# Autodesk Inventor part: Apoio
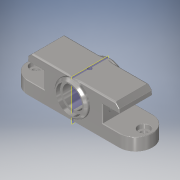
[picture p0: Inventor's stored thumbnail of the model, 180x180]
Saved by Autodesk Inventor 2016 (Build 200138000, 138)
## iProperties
Created: 2016-02
Part Number: Apoio
Material: Steel, Cast
Document SubType Name: Modeling
Designer: Vertex
Mass: 1273.57 g
Surface Area: 324.28 cm^2
Volume: 162.238 cm^3
Density: 7.85 g/cm^3
Appearance: Semi-Polished
Title: Apoio
Author: Vertex
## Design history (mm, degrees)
sketch "Sketch1"
  geometry: L1 (75, 45)-(25, 45); L2 (0, 15)-(0, 0); L3 (0, 15)-(40, 15); L4 (40, 35)-(40, 15); L5 (20, 35)-(40, 35); L6 (20, 40)-(20, 35); L7 (20, 40)-(25, 45); L8 (75, 45)-(125, 45); L9 (150, 15)-(150, 0); L10 (150, 15)-(110, 15); L11 (110, 35)-(110, 15); L12 (130, 35)-(110, 35); L13 (130, 40)-(130, 35); L14 (130, 40)-(125, 45); L15 (0, 0)-(150, 0); L16 (75, 50.194)-(75, -5); 5 further points
  constraints: 32 end point, 6 point on line, 2 parallel, 1 horizontal, 1 vertical
  dimensions: "d3" = 40 distance between parallel lines of L2 L4; "d5" = 5 distance of L6.start point (20, 45); "d6" = 5 distance of L1.end point (20, 45) (= d5); "d7" = 150 distance of L9.end L2.end; "d8" = 130 distance of point (140, 15) point (10, 15); "d9" = 20 distance between parallel lines of L12 L10; "d10" = 10 distance from line of L8 L12.start
extrude "Extrusion1" new body sketch "Sketch1" stored distance "d11" = 40; taper "d12" = 0 deg
hole "Hole1" diameter "d15" = 26; stored, may be unused: countersink angle "d19" = 90 deg, drill point angle "d21" = 118 deg; dims "d13" = 75, "d14" = 25, "d16" = 7.5, "d17" = 3.75, "d18" = 2.5, "d20" = 10
hole "Hole2" diameter "d24" = 8; stored, may be unused: countersink angle "d28" = 90 deg, drill point angle "d30" = 118 deg; dims "d22" = 10, "d23" = 20, "d25" = 7.5, "d26" = 13.5, "d27" = 5, "d29" = 10
workplane "Work Plane1"
mirror "Mirror1"
sketch "Sketch2"
  geometry: C1 r 20 at (75, 25); C2 r 16 at (75, 25); 2 further points
  constraints: 2 centre point, 2 coincident
  dimensions: "d34" = 40 diameter of C1; "d40" = 32 diameter of C2
extrude "Extrusion2" join sketch "Sketch2" distance "d35" = 5; taper "d36" = 0 deg
mirror "Mirror2"
chamfer "Chamfer3" distance "d41" = 2.5; stored, may be unused: second distance "d42" = 1.25, angle "d43" = 45 deg
fillet "Fillet1" dims "d65" = 2
fillet "Fillet2" dims "d45" = 1
fillet "Fillet3"
fillet "Fillet4"
hole "Hole3" diameter "d48" = 3; stored, may be unused: countersink angle "d52" = 90 deg, drill point angle "d54" = 118 deg; dims "d46" = 55, "d47" = 20, "d49" = 7.5, "d50" = 5, "d51" = 6, "d53" = 10
fillet "Fillet5" dims "d55" = 0.5
hole "Hole4" diameter "d58" = 4.92; stored, may be unused: countersink angle "d62" = 90 deg, drill point angle "d64" = 118 deg; dims "d56" = 10, "d57" = 10, "d59" = 12, "d60" = 3.75, "d61" = 2.5, "d63" = 17.1
mirror "Mirror4"
mirror "Mirror5"
fillet "Fillet6" dims "d66" = 0.5
body "Solid1"
